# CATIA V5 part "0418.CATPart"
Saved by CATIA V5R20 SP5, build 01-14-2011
Part number: Part3
Material "Brushed metal 2": density 7860 kg/m3, Young's modulus 2e+11 Pa, Poisson ratio 0.266
Material "DS Light Blue": density 7860 kg/m3, Young's modulus 2e+11 Pa, Poisson ratio 0.266
Material "DS Dark Green": density 7860 kg/m3, Young's modulus 2e+11 Pa, Poisson ratio 0.266
Material "DS Dark Red": density 7860 kg/m3, Young's modulus 2e+11 Pa, Poisson ratio 0.266
Material "Intensive Green": density 7860 kg/m3, Young's modulus 2e+11 Pa, Poisson ratio 0.266
Bounding box of the stored display mesh (mm): x -40 to 40, y -40 to 39.959, z 0 to 143.822
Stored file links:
  E:\0418.CATPart
  C:\Program Files\Dassault Systemes\B20\intel_a\startup\materials\Catalog.CATMaterial
  C:\Program Files\Dassault Systemes\B20\intel_a\startup\materials\blue_env_512x512.jpg
  C:\Program Files\Dassault Systemes\B20\intel_a\startup\materials\yellow_env_512x512.jpg
  C:\Program Files\Dassault Systemes\B20\intel_a\startup\materials\brushed_metal2.jpg
  C:\Program Files\Dassault Systemes\B20\intel_a\startup\materials\green_env_512x512.jpg
  C:\Program Files\Dassault Systemes\B20\intel_a\startup\materials\red_env_512x512.jpg
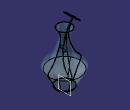
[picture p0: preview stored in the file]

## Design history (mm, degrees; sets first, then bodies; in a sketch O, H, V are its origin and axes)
Body1 (main body), material "DS Light Blue"
  Plane1: type Offset, RefPlane xy-plane, Offset 20
  Plane2: type Offset, RefPlane Plane1, Offset 20
  Plane3: type Offset, RefPlane Plane2, Offset 20
  Plane4: type Offset, RefPlane Plane3, Offset 20
  Plane5: type Offset, RefPlane Plane4, Offset 20
  Plane6: type Offset, RefPlane Plane5, Offset 20
  Sketch1 on Plane6, origin (0, 0, 120), H (1, 0, 0), V (0, 1, 0)
    circle A1 centre (0, 0) radius 16.2081
  Sketch2 on Plane5, origin (0, 0, 100), H (1, 0, 0), V (0, 1, 0)
    circle A1 centre (0, 0) radius 10.2388
    point P1 (10.2388, 0)
    coincidence: A1 P1, P1 H
  Sketch3 on Plane4, origin (0, 0, 80), H (1, 0, 0), V (0, 1, 0)
    circle A1 centre (0, 0) radius 15.4209
  Sketch4 on Plane3, origin (0, 0, 60), H (1, 0, 0), V (0, 1, 0)
    circle A1 centre (0, 0) radius 25
    point P1 (25, 0)
    coincidence: A1 P1, P1 H
  Sketch5 on Plane2, origin (0, 0, 40), H (1, 0, 0), V (0, 1, 0)
    circle A1 centre (0, 0) radius 40
  Sketch6 on Plane1, origin (0, 0, 20), H (1, 0, 0), V (0, 1, 0)
    circle A1 centre (0, 0) radius 30
  Sketch7 on xy-plane, origin (0, 0, 0), H (1, 0, 0), V (0, 1, 0)
    circle A1 centre (0, 0) radius 20
  Loft1: solid, Sections (Sketch1; Sketch2; Sketch3; Sketch4; Sketch5; Sketch6; Sketch7)
  Shell1: ExtOffset 0, Face face of Loft1, IntOffset 1
Body2, material "Brushed metal 2"
  Sketch8 on zx-plane, origin (0, 0, 0), H (-1, 0, 0), V (0, 0, 1)
    axis line L1 (0, -1.9669) -> (0, 144.1436)
    point P1 (0, -1.9669)
    point P3 (0, 34.5607)
    line L2 (0, 34.5607) -> (36.0644, 34.5607)
    line L3 (36.0644, 34.5607) -> (19.5671, 2.2405)
    line L4 (19.5671, 2.2405) -> (0, 2.2405)
    point P6 (0, 2.2405)
    coincidence: P1 V, P3 L1, P6 L1
    vertical: L1 V
    horizontal: L2 H, L4 H
  Shaft1: profile Sketch8, axis Sketch8.L1, angle 360
Body3, material "DS Dark Green"
  Sketch9 on zx-plane, origin (0, 0, 0), H (-1, 0, 0), V (0, 0, 1)
    arc A1 centre (98.8892, 65.5723) radius 102.4695 from (7.4819, 19.2612) to (20.1426, 131.139) cw
    arc A2 centre (-34.457, 97.6753) radius 34.6866 from (0, 101.6593) to (-17.1221, 127.7196) ccw
    point P5 (0, 101.6593)
    coincidence: P5 V
    tangency: A2 A1
  Plane7: type Normal, Curve Sketch9
  Sketch10 on Plane7, origin (-8.5771, 0, 75.7925), H (0, 1, 0), V (0.9937, 0, 0.1124)
    circle A1 centre (0, 12.0081) radius 1
    point P1 (0, 12.0081)
    coincidence: P1 V
  Rib1: profile Sketch10, centre curve Sketch9
Body4, material "DS Dark Red"
  Sketch11 on face of Rib1, origin (-72.7317, 0, 87.3518), H (0, -1, 0), V (0.7685, 0, 0.6399)
    point P1 (0, 73.7628)
    arc A1 centre (8.0613, 79.5734) radius 13.3408 from (-1.3704, 70.1385) to (-2.9861, 87.0521) cw
    point P5 (0, 68.9437)
    arc A2 centre (-7.4154, 78.095) radius 9.9924 from (-2.9861, 87.0521) to (-1.3704, 70.1385) cw
    coincidence: P1 V, P5 A1, P5 V
  Pad1: profile Sketch11, direction (-0.6399, 0, 0.7685), length 1
  Sketch12 on face of Rib1, origin (-72.7317, 0, 87.3518), H (0, -1, 0), V (0.7685, 0, 0.6399)
    arc A1 centre (14.7213, 70.3727) radius 13.4513 from (1.274, 70.0462) to (11.3591, 83.397) cw
    arc A2 centre (-4.6864, 85.0331) radius 16.1287 from (11.3591, 83.397) to (1.274, 70.0462) cw
  Pad2: profile Sketch12, direction (-0.6399, 0, 0.7685), length 1
  Sketch13 on face of Rib1, origin (-72.7317, 0, 87.3518), H (0, -1, 0), V (0.7685, 0, 0.6399)
    arc A1 centre (-13.0094, 66.8648) radius 10.7426 from (-2.5286, 69.222) to (-14.763, 77.4633) ccw
    arc A2 centre (-6.6581, 76.2934) radius 8.1889 from (-14.763, 77.4633) to (-2.5286, 69.222) ccw
    arc A3 centre (-8.1473, 67.0665) radius 6.8092 from (-1.3713, 67.7386) to (-13.0094, 62.2994) cw
    point P8 (-3.2852, 62.2994)
    arc A4 centre (9.3516, 62.3645) radius 9.4897 from (1.1086, 67.0665) to (2.4313, 55.8712) ccw
    point P10 (0, 60.7513)
    arc A5 centre (0.5956, 61.3301) radius 5.7593 from (1.1086, 67.0665) to (2.4313, 55.8712) cw
    arc A6 centre (9.6579, 61.6723) radius 11.7951 from (0.5956, 69.222) to (18.7202, 69.222) cw
    arc A7 centre (9.6579, 78.1458) radius 12.7185 from (18.7202, 69.222) to (0.5956, 69.222) cw
    arc A8 centre (-0.3686, 50.4228) radius 17.3448 from (-13.0094, 62.2994) to (-1.3713, 67.7386) cw
    coincidence: A3 P8, P8 A1, A4 P10, P10 V
    tangency: A6 A3
  Pad3: profile Sketch13, direction (-0.6399, 0, 0.7685), length 1
Body5, material "Intensive Green"
  Sketch14 on Plane7, origin (-8.5771, 0, 75.7925), H (0, 1, 0), V (0.9937, 0, 0.1124)
    arc A1 centre (-4.9962, 1.8693) radius 10.2144 from (-1.6809, 11.5307) to (-12.9921, 8.2255) ccw
    arc A2 centre (-7.8218, 11.5391) radius 6.141 from (-1.6809, 11.5307) to (-12.9921, 8.2255) cw
    arc A3 centre (6.9025, 12.4922) radius 5.7363 from (1.2459, 11.5391) to (7.9281, 18.1361) cw
    point P5 (6.9025, 12.4922)
    arc A4 centre (3.3953, 16.0447) radius 4.9921 from (1.2459, 11.5391) to (7.9281, 18.1361) ccw
    tangency: A3 A1
    coincidence: A4 P5
  Pad4: profile Sketch14, direction (0.1124, 0, -0.9937), length 1
Body6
